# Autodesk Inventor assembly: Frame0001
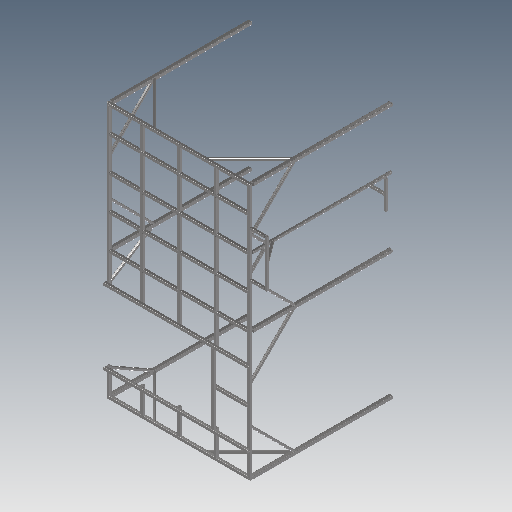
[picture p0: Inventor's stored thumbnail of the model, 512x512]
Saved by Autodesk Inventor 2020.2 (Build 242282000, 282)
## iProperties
Created: 2015-01
Part Number: Frame0001
Document SubType Name: Assembly
Designer: F.Stasiak
Mass: 417183 g
Surface Area: 261902 cm^2
Volume: 53144.3 cm^3
Density: 7.85 g/cm^3
Catalog Web Link: www.expertbooks.pl
Manager: www.cadconsulting.pl
Company: Fabian Stasiak CAD Consulting
Author: F.Stasiak
Subject: Zbiór ćwiczeń. Autodesk Inventor 2020. Kurs Professional
_FrameDoc: Frame Assembly
_Version: 15.0.0
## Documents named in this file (118)
- C:\2020_Kurs_Professional\R5 RamyMES\Platforma_wsporcza_700-100\Frame\Frame0001.iam
- C:\2020_Kurs_Professional\R5 RamyMES\Platforma_wsporcza_700-100\Frame\Skeleton0001.ipt
- C:\2020_Kurs_Professional\R5 RamyMES\Platforma_wsporcza_700-100\Frame\DIN 50x50x4 00000027.ipt
- DIN 50x50x4 00000027.ipt
- C:\2020_Kurs_Professional\R5 RamyMES\Platforma_wsporcza_700-100\Frame\DIN 50x50x4 00000028.ipt
- DIN 50x50x4 00000028.ipt
- C:\2020_Kurs_Professional\R5 RamyMES\Platforma_wsporcza_700-100\Frame\DIN 50x50x4 00000029.ipt
- DIN 50x50x4 00000029.ipt
- C:\2020_Kurs_Professional\R5 RamyMES\Platforma_wsporcza_700-100\Frame\DIN 50x50x4 00000030.ipt
- DIN 50x50x4 00000030.ipt
- C:\2020_Kurs_Professional\R5 RamyMES\Platforma_wsporcza_700-100\Frame\DIN 50x50x4 00000031.ipt
- DIN 50x50x4 00000031.ipt
- C:\2020_Kurs_Professional\R5 RamyMES\Platforma_wsporcza_700-100\Frame\DIN 50x50x4 00000032.ipt
- DIN 50x50x4 00000032.ipt
- C:\2020_Kurs_Professional\R5 RamyMES\Platforma_wsporcza_700-100\Frame\DIN 50x50x4 00000033.ipt
- DIN 50x50x4 00000033.ipt
- C:\2020_Kurs_Professional\R5 RamyMES\Platforma_wsporcza_700-100\Frame\DIN 50x50x4 00000034.ipt
- DIN 50x50x4 00000034.ipt
- C:\2020_Kurs_Professional\R5 RamyMES\Platforma_wsporcza_700-100\Frame\DIN 50x50x4 00000035.ipt
- DIN 50x50x4 00000035.ipt
- C:\2020_Kurs_Professional\R5 RamyMES\Platforma_wsporcza_700-100\Frame\DIN 50x50x4 00000036.ipt
- DIN 50x50x4 00000036.ipt
- C:\2020_Kurs_Professional\R5 RamyMES\Platforma_wsporcza_700-100\Frame\DIN 50x50x4 00000037.ipt
- DIN 50x50x4 00000037.ipt
- C:\2020_Kurs_Professional\R5 RamyMES\Platforma_wsporcza_700-100\Frame\DIN 50x50x4 00000038.ipt
- DIN 50x50x4 00000038.ipt
- C:\2020_Kurs_Professional\R5 RamyMES\Platforma_wsporcza_700-100\Frame\DIN 50x50x4 00000039.ipt
- DIN 50x50x4 00000039.ipt
- C:\2020_Kurs_Professional\R5 RamyMES\Platforma_wsporcza_700-100\Frame\DIN 50x50x4 00000040.ipt
- DIN 50x50x4 00000040.ipt
- C:\2020_Kurs_Professional\R5 RamyMES\Platforma_wsporcza_700-100\Frame\DIN 50x50x4 00000041.ipt
- DIN 50x50x4 00000041.ipt
- C:\2020_Kurs_Professional\R5 RamyMES\Platforma_wsporcza_700-100\Frame\DIN 50x50x4 00000042.ipt
- DIN 50x50x4 00000042.ipt
- C:\2020_Kurs_Professional\R5 RamyMES\Platforma_wsporcza_700-100\Frame\DIN 50x50x4 00000043.ipt
- DIN 50x50x4 00000043.ipt
- C:\2020_Kurs_Professional\R5 RamyMES\Platforma_wsporcza_700-100\Frame\DIN 50x50x4 00000044.ipt
- DIN 50x50x4 00000044.ipt
- C:\2020_Kurs_Professional\R5 RamyMES\Platforma_wsporcza_700-100\Frame\DIN 50x50x4 00000045.ipt
- DIN 50x50x4 00000045.ipt
- C:\2020_Kurs_Professional\R5 RamyMES\Platforma_wsporcza_700-100\Frame\DIN 50x50x4 00000046.ipt
- DIN 50x50x4 00000046.ipt
- C:\2020_Kurs_Professional\R5 RamyMES\Platforma_wsporcza_700-100\Frame\DIN 50x50x4 00000047.ipt
- DIN 50x50x4 00000047.ipt
- C:\2020_Kurs_Professional\R5 RamyMES\Platforma_wsporcza_700-100\Frame\DIN 50x50x4 00000048.ipt
- DIN 50x50x4 00000048.ipt
- C:\2020_Kurs_Professional\R5 RamyMES\Platforma_wsporcza_700-100\Frame\DIN 50x50x4 00000049.ipt
- DIN 50x50x4 00000049.ipt
- C:\2020_Kurs_Professional\R5 RamyMES\Platforma_wsporcza_700-100\Frame\DIN 40x40x2.9 00000050.ipt
- DIN 40x40x2.9 00000050.ipt
- C:\2020_Kurs_Professional\R5 RamyMES\Platforma_wsporcza_700-100\Frame\DIN 40x40x2.9 00000051.ipt
- DIN 40x40x2.9 00000051.ipt
- C:\2020_Kurs_Professional\R5 RamyMES\Platforma_wsporcza_700-100\Frame\DIN 40x40x2.9 00000052.ipt
- DIN 40x40x2.9 00000052.ipt
- C:\2020_Kurs_Professional\R5 RamyMES\Platforma_wsporcza_700-100\Frame\DIN 40x40x2.9 00000053.ipt
- DIN 40x40x2.9 00000053.ipt
- C:\2020_Kurs_Professional\R5 RamyMES\Platforma_wsporcza_700-100\Frame\DIN 40x40x2.9 00000054.ipt
- DIN 40x40x2.9 00000054.ipt
- C:\2020_Kurs_Professional\R5 RamyMES\Platforma_wsporcza_700-100\Frame\DIN 40x40x2.9 00000055.ipt
- DIN 40x40x2.9 00000055.ipt
- C:\2020_Kurs_Professional\R5 RamyMES\Platforma_wsporcza_700-100\Frame\DIN 40x40x2.9 00000056.ipt
- DIN 40x40x2.9 00000056.ipt
- C:\2020_Kurs_Professional\R5 RamyMES\Platforma_wsporcza_700-100\Frame\DIN 40x40x2.9 00000057.ipt
- DIN 40x40x2.9 00000057.ipt
- C:\2020_Kurs_Professional\R5 RamyMES\Platforma_wsporcza_700-100\Frame\DIN 40x40x2.9 00000058.ipt
- DIN 40x40x2.9 00000058.ipt
- C:\2020_Kurs_Professional\R5 RamyMES\Platforma_wsporcza_700-100\Frame\DIN 60x60x4 00000062.ipt
- DIN 80x80x4.5 00000005.ipt
- C:\2020_Kurs_Professional\R5 RamyMES\Platforma_wsporcza_700-100\Frame\DIN 60x60x4 00000063.ipt
- DIN 80x80x4.5 00000004.ipt
- C:\2020_Kurs_Professional\R5 RamyMES\Platforma_wsporcza_700-100\Frame\DIN 60x60x4 00000064.ipt
- DIN 80x80x4.5 00000003.ipt
- C:\2020_Kurs_Professional\R5 RamyMES\Platforma_wsporcza_700-100\Frame\DIN 40x40x4 00000074.ipt
- DIN 60x60x4 00000015.ipt
- C:\2020_Kurs_Professional\R5 RamyMES\Platforma_wsporcza_700-100\Frame\DIN 40x40x4 00000075.ipt
- DIN 60x60x4 00000016.ipt
- C:\2020_Kurs_Professional\R5 RamyMES\Platforma_wsporcza_700-100\Frame\DIN 40x40x4 00000076.ipt
- DIN 60x60x4 00000014.ipt
- C:\2020_Kurs_Professional\R5 RamyMES\Platforma_wsporcza_700-100\Frame\DIN 40x40x4 00000077.ipt
- DIN 60x60x4 00000013.ipt
- C:\2020_Kurs_Professional\R5 RamyMES\Platforma_wsporcza_700-100\Frame\DIN 40x40x4 00000078.ipt
- DIN 60x60x4 00000012.ipt
- C:\2020_Kurs_Professional\R5 RamyMES\Platforma_wsporcza_700-100\Frame\DIN 40x40x4 00000079.ipt
- DIN 60x60x4 00000011.ipt
- C:\2020_Kurs_Professional\R5 RamyMES\Platforma_wsporcza_700-100\Frame\DIN 40x40x4 00000080.ipt
- DIN 60x60x4 00000008.ipt
- C:\2020_Kurs_Professional\R5 RamyMES\Platforma_wsporcza_700-100\Frame\DIN 40x40x4 00000081.ipt
- DIN 60x60x4 00000009.ipt
- C:\2020_Kurs_Professional\R5 RamyMES\Platforma_wsporcza_700-100\Frame\DIN 40x40x4 00000082.ipt
- DIN 60x60x4 00000059.ipt
- C:\2020_Kurs_Professional\R5 RamyMES\Platforma_wsporcza_700-100\Frame\DIN 40x40x4 00000083.ipt
- DIN 60x60x4 00000007.ipt
- C:\2020_Kurs_Professional\R5 RamyMES\Platforma_wsporcza_700-100\Frame\DIN 40x40x4 00000084.ipt
- DIN 60x60x4 00000018.ipt
- C:\2020_Kurs_Professional\R5 RamyMES\Platforma_wsporcza_700-100\Frame\DIN 40x40x4 00000085.ipt
- DIN 60x60x4 00000017.ipt
- C:\2020_Kurs_Professional\R5 RamyMES\Platforma_wsporcza_700-100\Frame\DIN 50x50x4 00000100.ipt
- DIN 50x50x2.9 00000095.ipt
- C:\2020_Kurs_Professional\R5 RamyMES\Platforma_wsporcza_700-100\Frame\DIN 50x50x4 00000101.ipt
- DIN 50x50x2.9 00000096.ipt
- C:\2020_Kurs_Professional\R5 RamyMES\Platforma_wsporcza_700-100\Frame\DIN 50x50x4 00000102.ipt
- DIN 50x50x2.9 00000097.ipt
- C:\2020_Kurs_Professional\R5 RamyMES\Platforma_wsporcza_700-100\Frame\DIN 50x50x4 00000103.ipt
- DIN 50x50x2.9 00000098.ipt
- C:\2020_Kurs_Professional\R5 RamyMES\Platforma_wsporcza_700-100\Frame\DIN 50x50x4 00000104.ipt
- DIN 50x50x2.9 00000099.ipt
- C:\2020_Kurs_Professional\R5 RamyMES\Platforma_wsporcza_700-100\Frame\DIN 60x60x4 00000120.ipt
- DIN 70x70x5 00000117.ipt
- C:\2020_Kurs_Professional\R5 RamyMES\Platforma_wsporcza_700-100\Frame\DIN 60x60x4 00000121.ipt
- DIN 70x70x5 00000118.ipt
- C:\2020_Kurs_Professional\R5 RamyMES\Platforma_wsporcza_700-100\Frame\DIN 60x60x4 00000122.ipt
- DIN 70x70x5 00000119.ipt
- C:\2020_Kurs_Professional\R5 RamyMES\Platforma_wsporcza_700-100\Frame\DIN 50x50x4 00000123.ipt
- DIN 70x70x4 00000114.ipt
- C:\2020_Kurs_Professional\R5 RamyMES\Platforma_wsporcza_700-100\Frame\DIN 50x50x4 00000124.ipt
- DIN 70x70x4 00000115.ipt
- C:\2020_Kurs_Professional\R5 RamyMES\Platforma_wsporcza_700-100\Frame\DIN 50x50x4 00000125.ipt
- DIN 70x70x4 00000116.ipt
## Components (59 placed, 59 different names)
1. Model odniesienia ramy
2. DIN 60x60x4 00000121:1
3. DIN 60x60x4 00000122:1
4. DIN 60x60x4 00000064:1
5. DIN 60x60x4 00000063:1
6. DIN 60x60x4 00000062:1
7. DIN 60x60x4 00000120:1
8. DIN 40x40x4 00000083:1
9. DIN 40x40x4 00000080:1
10. DIN 40x40x4 00000081:1
11. DIN 40x40x4 00000079:1
12. DIN 40x40x4 00000078:1
13. DIN 40x40x4 00000077:1
14. DIN 40x40x4 00000076:1
15. DIN 40x40x4 00000074:1
16. DIN 40x40x4 00000075:1
17. DIN 40x40x4 00000085:1
18. DIN 40x40x4 00000084:1
19. DIN 50x50x4 00000101:1
20. DIN 50x50x4 00000102:1
21. DIN 50x50x4 00000103:1
22. DIN 50x50x4 00000104:1
23. DIN 50x50x4 00000100:1
24. DIN 50x50x4 00000125:1
25. DIN 50x50x4 00000124:1
26. DIN 50x50x4 00000027:1
27. DIN 50x50x4 00000028:1
28. DIN 50x50x4 00000029:1
29. DIN 50x50x4 00000030:1
30. DIN 50x50x4 00000031:1
31. DIN 50x50x4 00000032:1
32. DIN 50x50x4 00000033:1
33. DIN 50x50x4 00000034:1
34. DIN 50x50x4 00000035:1
35. DIN 50x50x4 00000036:1
36. DIN 50x50x4 00000037:1
37. DIN 50x50x4 00000038:1
38. DIN 50x50x4 00000039:1
39. DIN 50x50x4 00000040:1
40. DIN 50x50x4 00000041:1
41. DIN 50x50x4 00000042:1
42. DIN 50x50x4 00000043:1
43. DIN 50x50x4 00000044:1
44. DIN 50x50x4 00000045:1
45. DIN 50x50x4 00000046:1
46. DIN 50x50x4 00000047:1
47. DIN 50x50x4 00000048:1
48. DIN 50x50x4 00000049:1
49. DIN 40x40x2.9 00000050:1
50. DIN 40x40x2.9 00000051:1
51. DIN 40x40x2.9 00000052:1
52. DIN 40x40x2.9 00000053:1
53. DIN 40x40x2.9 00000054:1
54. DIN 40x40x2.9 00000055:1
55. DIN 40x40x2.9 00000056:1
56. DIN 40x40x2.9 00000057:1
57. DIN 40x40x2.9 00000058:1
58. DIN 40x40x4 00000082:1
59. DIN 50x50x4 00000123:1
